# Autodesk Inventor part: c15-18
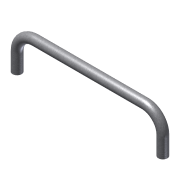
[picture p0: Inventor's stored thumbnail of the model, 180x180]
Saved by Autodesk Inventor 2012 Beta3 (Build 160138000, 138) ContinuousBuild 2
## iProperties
Created: 2011-02
Part Number: c15-18
Material: Default
Document SubType Name: Modeling
Designer: Beta-8540w
Density: 1 g/cm^3
Author: Beta-8540w
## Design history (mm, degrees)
sketch "Sketch1"
  geometry: L1 (-50.8, 0)-(-50.8, 12.7); L2 (-38.1, 25.4)-(38.1, 25.4); L3 (50.8, 12.7)-(50.8, 0); L4 (50.8, 0)-(-50.8, 0); A1 r 12.7 centre (-38.1, 12.7) between (-38.1, 25.4) and (-50.8, 12.7); A2 r 12.7 centre (38.1, 12.7) between (50.8, 12.7) and (38.1, 25.4); 2 further points
  constraints: 8 end point, 4 point on circle, 4 tangent, 2 centre point, 2 parallel, 1 coincident, 1 equal radius, 1 midpoint, 1 perpendicular, 1 vertical
  dimensions: "d0" = 101.6 distance of L3.end L1.start; "d1" = 25.4 distance between parallel lines of L4 L2; "d2" = 12.7 radius of A2
sketch "Sketch2"
  geometry: C1 r 3.175 at (-50.8, 0); 2 further points
  constraints: 1 centre point, 1 coincident
  dimensions: "d3" = 6.35 diameter of C1
sweep "Sweep1" sketch "Sketch1", "Sketch2" dims "d4" = 0
hole "Hole1" diameter "d7" = 3.302; stored, may be unused: countersink angle "d11" = 82 deg, drill point angle "d13" = 118 deg; dims "d5" = 25.4, "d6" = 25.4, "d8" = 9.652, "d9" = 9.525, "d10" = 6.35, "d12" = 12.7
hole "Hole2" diameter "d16" = 3.302; stored, may be unused: countersink angle "d20" = 82 deg, drill point angle "d22" = 118 deg; dims "d14" = 25.4, "d15" = 25.4, "d17" = 9.652, "d18" = 9.525, "d19" = 6.35, "d21" = 12.7
body "Solid1"
